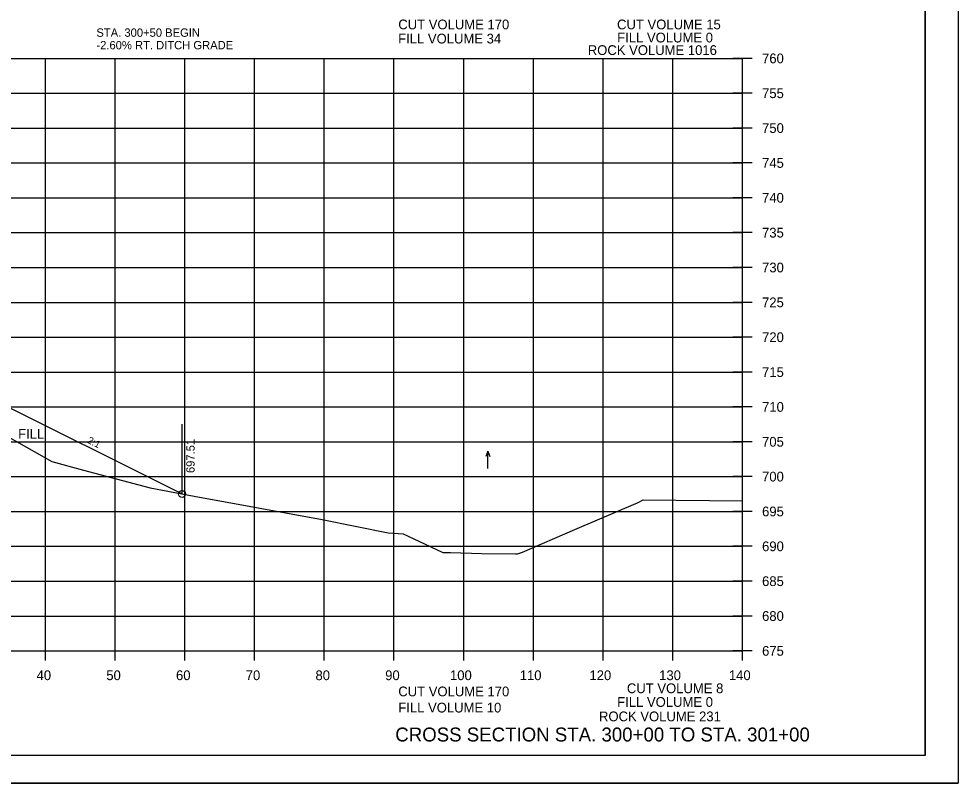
# Model space of a CAD drawing. Extents: x 1370515 to 1370849, y 383299 to 386073.
# Drawn here: x 1370714 to 1370848.7, y 383512.8 to 383622.4 of the extents above; entities that cross this region are included whole.
import ezdxf

# ---------------------------------------------------------------- set-up
doc = ezdxf.new("R2010")
doc.units = 0
for name, color, linetype in [('R_Axis', 7, 'Continuous'), ('R_Axis Annot', 7, 'Continuous'), ('R_Border', 7, 'Continuous'), ('R_Draft', 7, 'Continuous'), ('R_Drive', 7, 'Continuous'), ('R_Exist Surface', 7, 'Continuous'), ('R_Fin Surface', 7, 'Continuous'), ('R_Grid', 7, 'Continuous'), ('R_No Plot', 7, 'Continuous'), ('R_Water Annot', 7, 'Continuous'), ('R_Xsect Elev', 7, 'Continuous'), ('R_Xsect Slope', 7, 'Continuous')]:
    doc.layers.add(name, color=color, linetype=linetype)

msp = doc.modelspace()

# ---------------------------------------------------------------- linework, layer by layer
at = {"layer": 'R_Axis'}
for p, q in [((1370819.2, 383616.75), (1370816.4, 383616.75)), ((1370817.8, 383531.75), (1370817.8, 383616.75)), ((1370819.2, 383611.75), (1370816.4, 383611.75)), ((1370819.2, 383606.75), (1370816.4, 383606.75)), ((1370819.2, 383601.75), (1370816.4, 383601.75)), ((1370819.2, 383596.75), (1370816.4, 383596.75)), ((1370819.2, 383591.75), (1370816.4, 383591.75)), ((1370819.2, 383586.75), (1370816.4, 383586.75)), ((1370819.2, 383581.75), (1370816.4, 383581.75)), ((1370819.2, 383576.75), (1370816.4, 383576.75)), ((1370819.2, 383571.75), (1370816.4, 383571.75)), ((1370819.2, 383566.75), (1370816.4, 383566.75)), ((1370819.2, 383561.75), (1370816.4, 383561.75)), ((1370819.2, 383556.75), (1370816.4, 383556.75)), ((1370819.2, 383551.75), (1370816.4, 383551.75)), ((1370819.2, 383546.75), (1370816.4, 383546.75)), ((1370819.2, 383541.75), (1370816.4, 383541.75)), ((1370819.2, 383536.75), (1370816.4, 383536.75)), ((1370717.8, 383530.35), (1370717.8, 383533.15)), ((1370727.8, 383530.35), (1370727.8, 383533.15)), ((1370737.8, 383530.35), (1370737.8, 383533.15)), ((1370747.8, 383530.35), (1370747.8, 383533.15)), ((1370757.8, 383530.35), (1370757.8, 383533.15)), ((1370767.8, 383530.35), (1370767.8, 383533.15)), ((1370777.8, 383530.35), (1370777.8, 383533.15)), ((1370787.8, 383530.35), (1370787.8, 383533.15)), ((1370797.8, 383530.35), (1370797.8, 383533.15)), ((1370807.8, 383530.35), (1370807.8, 383533.15)), ((1370817.8, 383530.35), (1370817.8, 383533.15)), ((1370537.8, 383531.75), (1370817.8, 383531.75)), ((1370819.2, 383531.75), (1370816.4, 383531.75))]:
    msp.add_line(p, q, dxfattribs=at)
at = {"layer": 'R_Border'}
for q in [(1370843.98, 383722.21), (1370527.8, 383516.75)]:
    msp.add_line((1370843.98, 383516.75), q, dxfattribs=at)
at = {"layer": 'R_Exist Surface'}
msp.add_lwpolyline([(1370712.58, 383562.42), (1370718.74, 383558.93), (1370723.27, 383557.68), (1370732.84, 383555.13), (1370739.13, 383553.93), (1370757.48, 383550.62), (1370766.97, 383548.68), (1370769.1, 383548.52), (1370771.36, 383547.5), (1370774.8, 383545.86), (1370775.91, 383545.88), (1370780.39, 383545.71), (1370785.23, 383545.66), (1370785.5, 383545.67), (1370786.25, 383545.92), (1370793.73, 383549.17), (1370802.85, 383553.03), (1370803.53, 383553.41), (1370817.8, 383553.27)], dxfattribs=at)
at = {"layer": 'R_Fin Surface'}
msp.add_lwpolyline([(1370619.13, 383582.5), (1370648.4, 383572.75), (1370651.8, 383573.88), (1370657.8, 383575.38), (1370665.8, 383574.82), (1370677.8, 383573.97), (1370689.8, 383573.12), (1370697.8, 383572.56), (1370703.8, 383571.06), (1370709.13, 383568.4), (1370737.41, 383554.26)], dxfattribs=at)
at = {"layer": 'R_Grid'}
for p, q in [((1370537.8, 383616.75), (1370817.8, 383616.75)), ((1370717.8, 383531.75), (1370717.8, 383616.75)), ((1370727.8, 383531.75), (1370727.8, 383616.75)), ((1370737.8, 383531.75), (1370737.8, 383616.75)), ((1370747.8, 383531.75), (1370747.8, 383616.75)), ((1370757.8, 383531.75), (1370757.8, 383616.75)), ((1370767.8, 383531.75), (1370767.8, 383616.75)), ((1370777.8, 383531.75), (1370777.8, 383616.75)), ((1370787.8, 383531.75), (1370787.8, 383616.75)), ((1370797.8, 383531.75), (1370797.8, 383616.75)), ((1370807.8, 383531.75), (1370807.8, 383616.75)), ((1370817.8, 383531.75), (1370817.8, 383616.75)), ((1370537.8, 383611.75), (1370817.8, 383611.75)), ((1370537.8, 383606.75), (1370817.8, 383606.75)), ((1370537.8, 383601.75), (1370817.8, 383601.75)), ((1370537.8, 383596.75), (1370817.8, 383596.75)), ((1370537.8, 383591.75), (1370817.8, 383591.75)), ((1370537.8, 383586.75), (1370817.8, 383586.75)), ((1370537.8, 383581.75), (1370817.8, 383581.75)), ((1370537.8, 383576.75), (1370817.8, 383576.75)), ((1370537.8, 383571.75), (1370817.8, 383571.75)), ((1370537.8, 383566.75), (1370817.8, 383566.75)), ((1370537.8, 383561.75), (1370817.8, 383561.75)), ((1370537.8, 383556.75), (1370817.8, 383556.75)), ((1370537.8, 383551.75), (1370817.8, 383551.75)), ((1370537.8, 383546.75), (1370817.8, 383546.75)), ((1370537.8, 383541.75), (1370817.8, 383541.75)), ((1370537.8, 383536.75), (1370817.8, 383536.75)), ((1370537.8, 383531.75), (1370817.8, 383531.75))]:
    msp.add_line(p, q, dxfattribs=at)
at = {"layer": 'R_No Plot'}
msp.add_line((1370515.4, 383512.77), (1370848.73, 383512.77), dxfattribs=at)
for points in [[(1370515.39, 383726.1), (1370848.73, 383726.1), (1370848.73, 383512.76), (1370515.39, 383512.76)], [(1370761.72, 383722.21), (1370761.72, 383712.33), (1370797.45, 383712.33), (1370797.45, 383709.41), (1370820.65, 383709.41), (1370820.65, 383686.19), (1370843.98, 383686.19), (1370843.98, 383516.75), (1370527.8, 383516.75), (1370527.8, 383722.21)]]:
    msp.add_lwpolyline(points, close=True, dxfattribs=at)
msp.add_circle((1370737.41, 383554.26), 0.5, dxfattribs=at)
at = {"layer": 'R_Water Annot'}
for p, q in [((1370781.27, 383560.41), (1370780.99, 383559.64)), ((1370781.27, 383557.9), (1370781.27, 383560.41)), ((1370781.27, 383560.41), (1370781.55, 383559.64))]:
    msp.add_line(p, q, dxfattribs=at)
at = {"layer": 'R_Xsect Elev'}
msp.add_line((1370737.41, 383554.26), (1370737.41, 383564.26), dxfattribs=at)

# ---------------------------------------------------------------- texts
at = {"layer": 'R_Axis Annot'}
for s, p in [('CUT VOLUME 170', (1370768.42, 383620.92)), ('CUT VOLUME 15', (1370799.8, 383620.92)), ('FILL VOLUME 34', (1370768.4, 383618.89)), ('FILL VOLUME 0', (1370799.82, 383619.04)), ('ROCK VOLUME 1016', (1370795.6, 383617.24)), ('760', (1370820.6, 383616.05)), ('755', (1370820.6, 383611.05)), ('750', (1370820.6, 383606.05)), ('745', (1370820.6, 383601.05)), ('740', (1370820.6, 383596.05)), ('735', (1370820.6, 383591.05)), ('730', (1370820.6, 383586.05)), ('725', (1370820.6, 383581.05)), ('720', (1370820.6, 383576.05)), ('715', (1370820.6, 383571.05)), ('710', (1370820.6, 383566.05)), ('FILL', (1370713.89, 383562.2)), ('705', (1370820.6, 383561.05)), ('700', (1370820.6, 383556.05)), ('695', (1370820.6, 383551.05)), ('690', (1370820.6, 383546.05)), ('685', (1370820.6, 383541.05)), ('680', (1370820.6, 383536.05)), ('675', (1370820.6, 383531.05)), ('40', (1370716.54, 383527.55)), ('50', (1370726.54, 383527.55)), ('60', (1370736.54, 383527.55)), ('70', (1370746.54, 383527.55)), ('80', (1370756.54, 383527.55)), ('90', (1370766.54, 383527.55)), ('100', (1370775.84, 383527.55)), ('110', (1370785.84, 383527.55)), ('120', (1370795.84, 383527.55)), ('130', (1370805.84, 383527.55)), ('140', (1370815.84, 383527.55)), ('CUT VOLUME 170', (1370768.42, 383525.23)), ('CUT VOLUME 8', (1370801.21, 383525.68)), ('FILL VOLUME 0', (1370799.82, 383523.72)), ('FILL VOLUME 10', (1370768.42, 383522.91)), ('ROCK VOLUME 231', (1370797.21, 383521.65))]:
    msp.add_text(s, height=1.4, dxfattribs=at).set_placement(p)
at = {"layer": 'R_Draft'}
msp.add_text('CROSS SECTION STA. 300+00 TO STA. 301+00', height=2, dxfattribs=at).set_placement((1370767.99, 383518.75))
at = {"layer": 'R_Drive'}
for s, p in [('STA. 300+50 BEGIN', (1370725.12, 383619.85)), ('-2.60% RT. DITCH GRADE', (1370725.12, 383618.05))]:
    msp.add_text(s, height=1.2, dxfattribs=at).set_placement(p)
at = {"layer": 'R_No Plot'}
for p in [(1370718.69, 383558.88), (1370732.8, 383555.08), (1370803.49, 383553.36), (1370769.05, 383548.47), (1370774.76, 383545.81), (1370780.35, 383545.66), (1370785.45, 383545.62)]:
    msp.add_text('+', height=0.1, dxfattribs=at).set_placement(p)
at = {"layer": 'R_Xsect Elev'}
msp.add_text('697.51', height=1.2, rotation=90, dxfattribs=at).set_placement((1370739.21, 383557.26))
at = {"layer": 'R_Xsect Slope'}
msp.add_text('2:1', height=1, rotation=333.4349, dxfattribs=at).set_placement((1370723.73, 383561.65))

doc.saveas('drawing.dxf')
